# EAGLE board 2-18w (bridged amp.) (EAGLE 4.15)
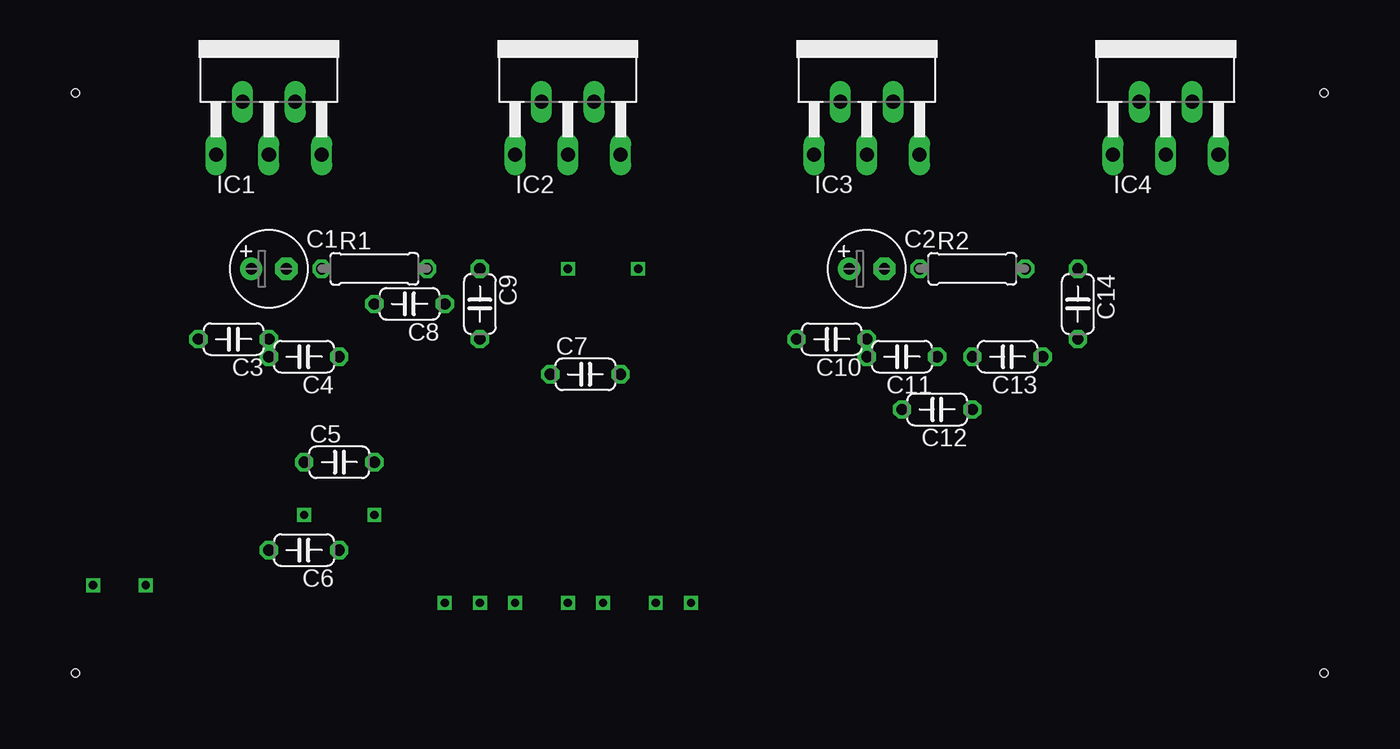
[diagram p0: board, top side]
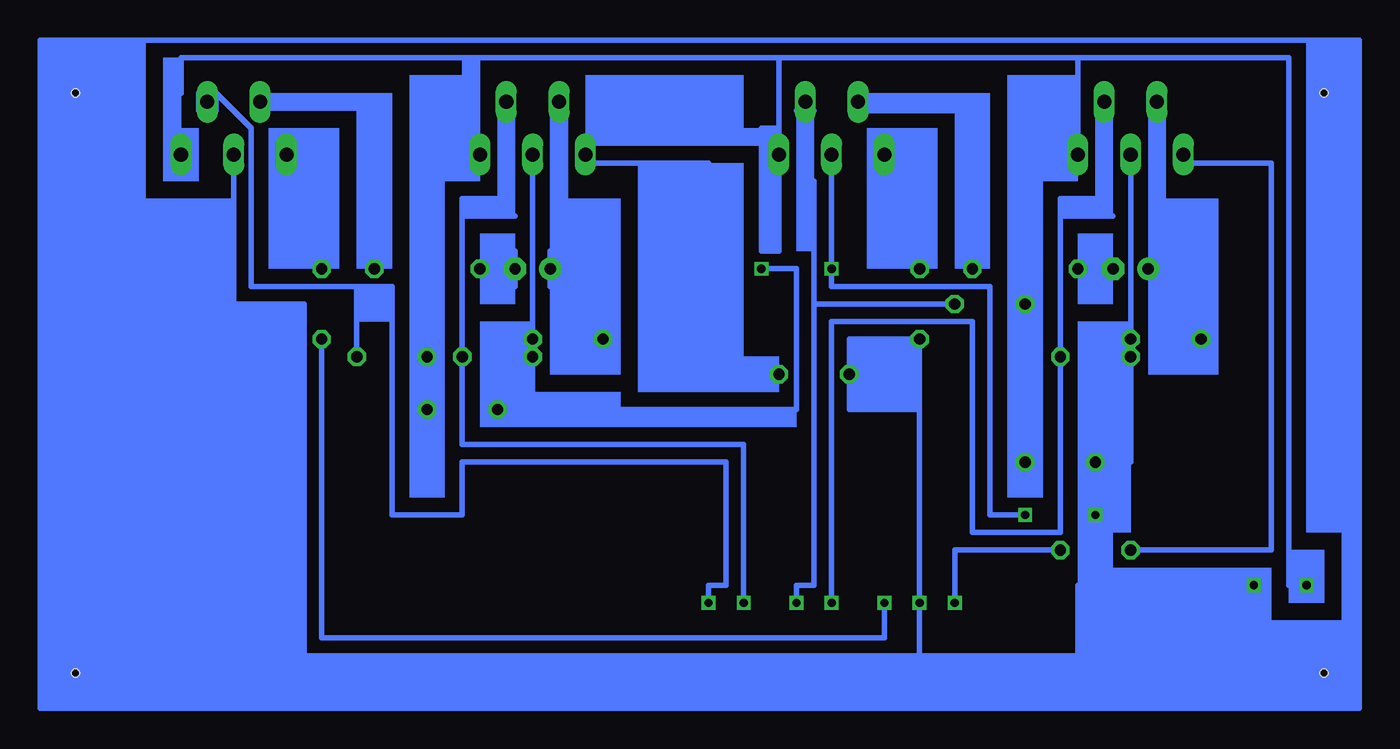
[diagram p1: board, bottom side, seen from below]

No outline drawn. Coordinates in mm, seen from the top.
Copper layers (1*16): Top 0.035mm / dielectric 1.5mm / Bottom 0.035mm
Design rules "default": minimum track width 10mil, minimum drill 24mil, track to track 7mil, track to pad 8mil, pad to pad 8mil, via to via 8mil, smd to smd 8mil, copper to edge 40mil, drill to drill 8mil, minimum pad ring 10mil, minimum via ring 8mil, stop-mask expansion 4mil, vias tented up to drill 0mil, thermal gap 10mil
Holes 0.6 mm at -6.35,38.1 -6.35,80.01 83.82,80.01 83.82,38.1

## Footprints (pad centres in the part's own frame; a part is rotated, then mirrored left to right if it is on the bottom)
E2,5-6 = drill 0.813 pad 1.6 round: + -1.27,0 | drill 0.813 pad 1.6 octagon: - 1.27,0
C050-024X044 = drill 0.813 octagon: 1 -2.54,0; 2 2.54,0
CB360 = drill 1.016 long: 1 -3.81,-8.255; 2 -1.905,-4.445; 3 0,-8.255; 4 1.905,-4.445; 5 3.81,-8.255
0207/7 = drill 0.813 octagon: 1 -3.81,0; 2 3.81,0

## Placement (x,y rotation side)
C1  10uf  [E2,5-6]  7.62,67.31 0 top
C2  10uF  [E2,5-6]  50.8,67.31 0 top
C3  1nF  [C050-024X044]  5.08,62.23 180 top
C4  0,1uF  [C050-024X044]  10.16,60.96 180 top
C5  0,1uF  [C050-024X044]  12.7,53.34 0 top
C6  0,1uF  [C050-024X044]  10.16,46.99 180 top
C7  0,1uF  [C050-024X044]  30.48,59.69 0 top
C8  620ohm  [C050-024X044]  17.78,64.77 180 top
C9  0,1uF  [C050-024X044]  22.86,64.77 270 top
C10  1nF  [C050-024X044]  48.26,62.23 180 top
C11  0,1uF  [C050-024X044]  53.34,60.96 180 top
C12  0,1uF  [C050-024X044]  55.88,57.15 180 top
C13  0,1uF  [C050-024X044]  60.96,60.96 180 top
C14  0,1uF  [C050-024X044]  66.04,64.77 270 top
IC1  TDA2003V  [CB360]  7.62,83.82 0 top
IC2  TDA2003V  [CB360]  29.21,83.82 0 top
IC3  TDA2003V  [CB360]  50.8,83.82 0 top
IC4  TDA2003V  [CB360]  72.39,83.82 0 top
R1  [0207/7]  15.24,67.31 0 top
R2  620ohm  [0207/7]  58.42,67.31 0 top

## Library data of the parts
C1-C14 R1 R2 = rcl
IC1-IC4 = linear

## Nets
GND: C9.2
L: C6.1
R: C14.2
R-: C13.1
S$2: C1.+ C3.2
S$3: C1.- R1.1
S$5: R1.2
S$6: IC1.2
S$10: C10.1
S$13: C5.1

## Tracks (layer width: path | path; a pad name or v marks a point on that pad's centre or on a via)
GND  (via drill 0.6)
  Bottom 0.406: 22.86,57.15 v22.86,43.18 22.86,38.1 | 22.86,57.15 27.94,57.15 27.94,62.23 C9.2 22.86,57.15
L  (via drill 0.6)
  Bottom 0.406: C6.1 20.32,46.99 v20.32,43.18
L+  (via drill 0.6)
  Bottom 0.406: 12.7,72.39 10.16,72.39 | 11.43,71.12 10.16,71.12 | 11.43,71.12 8.89,71.12 | 11.43,71.12 12.7,72.39 | 12.7,71.12 11.43,71.12 | 12.7,71.12 12.7,72.39 | 12.7,71.12 12.7,48.26 19.05,48.26 19.05,63.5 29.21,63.5 29.21,53.34 | 29.21,53.34 v29.21,43.18 | 29.21,53.34 29.21,57.15
L-  (via drill 0.6)
  Bottom 0.406: 30.48,64.77 30.48,44.45 31.75,44.45 v31.75,43.18 | 30.48,68.58 30.48,64.77 | 30.48,64.77 30.48,73.66 | 20.32,64.77 30.48,64.77
R  (via drill 0.6)
  Bottom 0.406: C14.2 66.04,40.64 25.4,40.64 v25.4,43.18
R+  (via drill 0.6)
  Bottom 0.406: 55.88,71.12 52.07,71.12 | 55.88,71.12 55.88,72.39 53.34,72.39 | 55.88,71.12 55.88,54.61 35.56,54.61 v35.56,43.18
R-  (via drill 0.6)
  Bottom 0.406: 63.5,66.04 71.12,66.04 71.12,77.47 73.66,80.01 | 63.5,66.04 C13.1 | 63.5,66.04 60.96,66.04 60.96,49.53 | 60.96,49.53 58.42,49.53 | 60.96,49.53 55.88,49.53 55.88,53.34 36.83,53.34 36.83,44.45 38.1,44.45 v38.1,43.18 | 73.66,80.01 74.93,80.01 74.93,78.74 73.66,78.74 73.66,80.01
S$1
  Bottom 0.406: 3.81,74.93 -2.54,74.93 -2.54,46.99 7.62,46.99
S$2
  Bottom 0.406: C1.+ 2.54,67.31 C3.2
S$3
  Bottom 0.406: C1.- R1.1
S$5
  Bottom 0.406: 26.67,78.74 19.05,78.74 R1.2
S$6
  Top 0.254: IC1.2 6.35,78.74
S$7  (via drill 0.6)
  Bottom 0.406: 29.21,76.2 v29.21,67.31 29.21,66.04 17.78,66.04 17.78,49.53 v15.24,49.53
S$9
  Bottom 0.406: 25.4,74.93 22.86,74.93 22.86,67.31
S$13
  Bottom 0.406: 7.62,74.93 7.62,53.34 C5.1
S$14  (via drill 0.6)
  Bottom 0.406: 10.16,48.26 10.16,44.45 v-1.27,44.45
S$15  (via drill 0.6)
  other vias: 10.16,49.53
S$17  (via drill 0.6)
  other vias: -5.08,44.45
S$18
  Bottom 0.406: 50.8,74.93 50.8,58.42
S$21
  Bottom 0.406: 49.53,68.58 49.53,66.04
S$22
  Bottom 0.406: 52.07,68.58 52.07,66.04
S$23
  Bottom 0.406: 39.37,74.93 46.99,74.93
S$25
  Bottom 0.406: 33.02,72.39 33.02,76.2 | 33.02,76.2 33.02,77.47 34.29,77.47 34.29,73.66 | 33.02,72.39 34.29,72.39 34.29,73.66 | 33.02,72.39 33.02,68.58 34.29,68.58 34.29,73.66 | 15.24,53.34 15.24,74.93 11.43,74.93 11.43,82.55 | 76.2,80.01 76.2,82.55 33.02,82.55 | -3.81,44.45 -3.81,82.55 11.43,82.55 | 33.02,82.55 11.43,82.55 | 33.02,76.2 33.02,82.55
S$26
  Bottom 0.406: 41.91,71.12 41.91,74.93 38.1,74.93
S$27  (via drill 0.6)
  Bottom 0.406: v34.29,67.31 31.75,67.31 31.75,57.15 41.91,57.15 | 41.91,57.15 45.72,57.15 | 41.91,57.15 53.34,57.15
S$28
  Bottom 0.406: 31.75,78.74 30.48,78.74
S$30
  Bottom 0.406: 72.39,74.93 72.39,64.77 67.31,64.77 67.31,39.37 11.43,39.37 11.43,44.45
S$31
  Bottom 0.406: -8.89,83.82 86.36,83.82 86.36,35.56 -8.89,35.56 -8.89,83.82
(copper drawn outside any net)
  shapes: Bottom area x76

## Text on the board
Bottom: +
